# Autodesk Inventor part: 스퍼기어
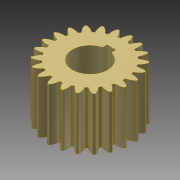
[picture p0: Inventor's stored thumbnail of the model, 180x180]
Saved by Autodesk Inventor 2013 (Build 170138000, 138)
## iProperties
Created: 2023-11
Part Number: 스퍼기어
Material: 알루미늄 6061
Document SubType Name: Modeling
Designer: mdu-01
Density: 1 g/cm^3
Author: mdu-01
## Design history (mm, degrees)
sketch "스케치1" dims "d2" = 44, "d5" = 2.5
  geometry: L1 (-2.5, 9.682)-(2.5, 9.682); L2 (2.5, 9.682)-(2.5, 12.3); L3 (2.5, 12.3)-(-2.5, 12.3); L4 (-2.5, 12.3)-(-2.5, 9.682); L5 (0, 0)-(0, 9.682); A1 r 10 centre (0, 0) between (-2.5, 9.682) and (2.5, 9.682); A2 r 24 centre (0, 0) between (0.57, 23.993) and (-0.57, 23.993); A3 r 9.393 centre (-7.31, 18.88) between (2.07, 19.39) and (0.57, 23.993); A4 r 9.393 centre (7.31, 18.88) between (-0.57, 23.993) and (-2.07, 19.39); A5 r 19.5 centre (0, 0) between (2.07, 19.39) and (-2.07, 19.39); 2 further points
  constraints: 11 point on circle, 10 end point, 5 centre point, 3 coincident, 3 symmetric about line, 2 parallel, 1 horizontal, 1 midpoint, 1 perpendicular, 7 other
  dimensions: "d0" = 20 diameter of A1; "d3" = 5 distance between parallel lines of L2 L4; "d4" = 2.3 distance edge to line of A1 L3; "d6" = 2 dimension on A2; "d7" = 1.57 horizontal distance of point (1.57, 21.944) L5.start; "d8" = 1 horizontal distance of A2.start point (1.57, 21.944); "d9" = 0.5 horizontal distance of point (1.57, 21.944) A3.start
extrude "돌출1" new body sketch "스케치1" distance "d10" = 30; taper "d11" = 0 deg
extrude "돌출2" join sketch "스케치1" distance "d12" = 30; taper "d13" = 0 deg
fillet "모깎기1" dims "d14" = 0.25
node "솔리드1"
pattern_circular "원형 패턴1" dims angle "d16" = 360 deg
